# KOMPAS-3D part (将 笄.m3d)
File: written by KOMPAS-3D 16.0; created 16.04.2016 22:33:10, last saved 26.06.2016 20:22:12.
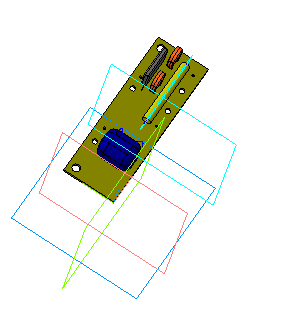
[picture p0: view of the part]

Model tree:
1. Эскиз:1
2. Операция выдавливания:1
     Расстояние 1 = 1; Расстояние 2 = 20
3. Эскиз:2
4. Операция выдавливания:2
     Расстояние 1 = 7; Расстояние 2 = 20
5. Скругление:1
     Радиус = 3
6. Эскиз:3
7. Операция выдавливания:3
     Расстояние 1 = 4; Расстояние 2 = 20
8. Эскиз:4
9. Операция выдавливания:4
     Расстояние 1 = 8; Расстояние 2 = 20
10. Скругление:2
     Радиус = 0.5
11. Смещенная плоскость:1
     Расстояние = 31
12. Эскиз:5
13. Операция выдавливания:5
     Расстояние 1 = 8; Расстояние 2 = 25
14. Смещенная плоскость:2
     Расстояние = 11
15. Эскиз:7
16. Операция выдавливания:6
     Расстояние 1 = 2; Угол 1 = 1; Расстояние 2 = 1
17. Скругление:5
     Радиус = 0.2
18. Нормальная плоскость:1
19. Эскиз:14
20. Операция выдавливания:8
     Расстояние 1 = 8; Расстояние 2 = 0.3
21. Сплайн:3
     Координата X = 21.0418; Координата Y = 5.02005; Координата Z = 5; Координата X = 23; Координата Y = 4; Координата Z = 4; Координата X = 23; Координата Y = 3; Координата Z = 1; Порядок = 4
22. Сплайн:4
     Координата X = 21.0418; Координата Y = 12.0201; Координата Z = 5; Координата X = 23; Координата Y = 12; Координата Z = 4; Координата X = 23; Координата Y = 11; Координата Z = 1; Порядок = 4
23. Эскиз:15
24. Кинематическая операция:5
25. Эскиз:16
26. Кинематическая операция:6
27. Эскиз:18
28. Сплайн:5
     Координата X = 31; Координата Y = 6.7878; Координата Z = 2.59474; Координата X = 30; Координата Y = 7; Координата Z = 2; Координата X = 30; Координата Y = 7; Координата Z = 1; Порядок = 4
29. Кинематическая операция:7
30. Эскиз:19
31. Сплайн:6
     Координата X = 56; Координата Y = 6.7878; Координата Z = 2.64474; Координата X = 57; Координата Y = 7; Координата Z = 2; Координата X = 57; Координата Y = 7; Координата Z = 1; Порядок = 4
32. Кинематическая операция:8

Expressions: P758713837-1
